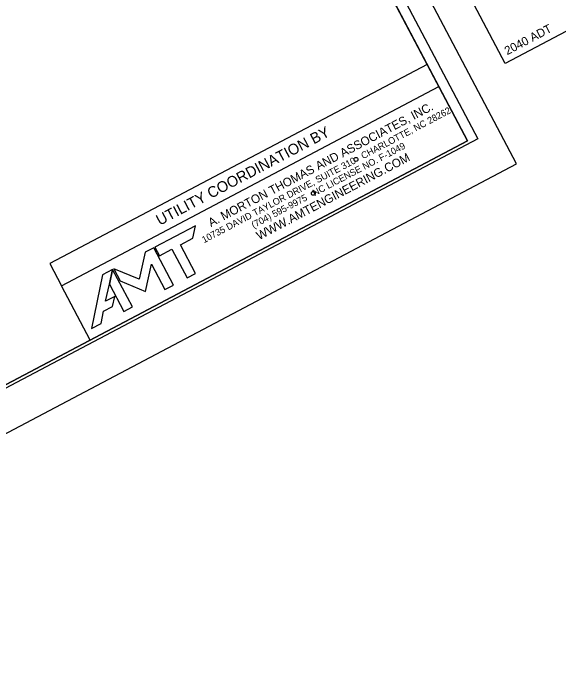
# Model space of a CAD drawing. Extents: x 1487051 to 1489241, y 497582 to 499399.
# Drawn here: x 1488789 to 1489072.9, y 498102.7 to 498446.4 of the extents above; entities that cross this region are included whole.
import ezdxf

# ---------------------------------------------------------------- set-up
doc = ezdxf.new("R2010")
doc.units = 0
for name, color, linetype in [('COGO Default Point Elevation', 7, 'Continuous'), ('Exist DTM Regular Point Cogo Elevation', 7, 'Continuous'), ('Exist Other Culture Sign Post Cogo Comment', 7, 'Continuous'), ('Exist Other Culture Sign Post Cogo Number', 7, 'Continuous'), ('Exist Roads EOP Cogo Point CELL', 7, 'Continuous'), ('Exist Structure Minor Pipes RCP 15 Inch Cogo Comment', 7, 'Continuous'), ('Exist Vegetation Woods Line Cogo Elevation', 7, 'Continuous'), ('Exist Vegetation Woods Line Cogo Number', 7, 'Continuous')]:
    doc.layers.add(name, color=color, linetype=linetype)

msp = doc.modelspace()

# ---------------------------------------------------------------- linework, layer by layer
at = {"layer": 'Exist DTM Regular Point Cogo Elevation'}
for points in [[(1487214.01, 498609.18), (1488227.42, 499144.32), (1488970.72, 498494.78), (1489030.74, 498381.1), (1487704.3, 497680.71)], [(1487208.66, 498608.09), (1488222.07, 499143.23), (1488965.37, 498493.68), (1489025.39, 498380), (1487698.94, 497679.61)], [(1487208.66, 498608.09), (1488222.07, 499143.23), (1488965.37, 498493.68), (1489025.39, 498380), (1487698.94, 497679.61)]]:
    msp.add_lwpolyline(points, close=True, dxfattribs=at)
at = {"layer": 'Exist Other Culture Sign Post Cogo Comment'}
msp.add_lwpolyline([(1488264.23, 499106.38), (1488223.12, 499143.79), (1487208.65, 498608.11), (1487698.94, 497679.61), (1489025.4, 498380.01), (1488871.95, 498670.61), (1488744.3, 498686.86)], close=True, dxfattribs=at)
at = {"layer": 'Exist Roads EOP Cogo Point CELL'}
msp.add_lwpolyline([(1487562.23, 497581.96), (1489050.94, 498368.04), (1488539.66, 499336.34), (1487050.94, 498550.27)], close=True, dxfattribs=at)
at = {"layer": 'Exist Structure Minor Pipes RCP 15 Inch Cogo Comment'}
for points in [[(1488535.14, 499308.53), (1487208.67, 498608.12), (1487698.94, 497679.61), (1489025.4, 498380.01)], [(1487698.94, 497679.61), (1487208.66, 498608.09), (1488358.21, 499215.12), (1488375.74, 499181.9), (1488552.62, 499275.32), (1489025.4, 498380.01)]]:
    msp.add_lwpolyline(points, close=True, dxfattribs=at)
at = {"layer": 'Exist Vegetation Woods Line Cogo Elevation'}
for points in [[(1488981.95, 498539.84), (1489169.07, 498638.65), (1489232.18, 498519.12), (1489045.06, 498420.32)], [(1488814.13, 498304.59), (1489010.48, 498408.27), (1489004.39, 498419.8), (1488808.04, 498316.13)], [(1488814.13, 498304.59), (1489010.48, 498408.27), (1489025.4, 498380.01), (1488829.05, 498276.33)]]:
    msp.add_lwpolyline(points, close=True, dxfattribs=at)
at = {"layer": 'Exist Vegetation Woods Line Cogo Number'}
msp.add_lwpolyline([(1488814.13, 498304.59), (1489010.48, 498408.27), (1489025.4, 498380.01), (1488829.05, 498276.33)], close=True, dxfattribs=at)
for points in [[(1488883.93, 498311.01), (1488876.03, 498325.97), (1488882.48, 498329.38), (1488883.85, 498335.8), (1488862.72, 498324.64), (1488865.08, 498320.19), (1488871.58, 498323.62), (1488879.48, 498308.66), (1488883.93, 498311.01)], [(1488857.9, 498301.64), (1488860.96, 498315.83), (1488867.95, 498302.58), (1488872.41, 498304.93), (1488862.16, 498324.34), (1488857.7, 498321.99), (1488854.57, 498307.95), (1488841.3, 498313.33), (1488844.56, 498307.15), (1488857.9, 498301.64)], [(1488839.03, 498305.46), (1488840.73, 498313.03), (1488835.53, 498310.28), (1488829.66, 498282.36), (1488834.7, 498285.02), (1488836.01, 498291.29), (1488840.63, 498293.73), (1488841.86, 498299.07), (1488837.08, 498296.55), (1488839.03, 498305.46)], [(1488850.98, 498293.61), (1488840.73, 498313.03), (1488839.03, 498305.46), (1488846.53, 498291.26), (1488850.98, 498293.61)]]:
    msp.add_lwpolyline(points, dxfattribs=at)
for centre in [(1488967.39, 498370.33), (1488945.15, 498352.67)]:
    msp.add_circle(centre, 1, dxfattribs=at)

# ---------------------------------------------------------------- texts
at = {"layer": 'COGO Default Point Elevation'}
msp.add_text('UTILITY COORDINATION BY', height=5.625, rotation=27.8351, dxfattribs=at).set_placement((1488865.23, 498335.77))
at = {"layer": 'Exist Other Culture Sign Post Cogo Number'}
msp.add_text('2040 ADT', height=4.444, rotation=27.8404, dxfattribs=at).set_placement((1489046.1, 498424.51))
at = {"layer": 'Exist Vegetation Woods Line Cogo Number'}
for s, height, p in [('10735 DAVID TAYLOR DRIVE, SUITE 310   CHARLOTTE, NC 28262', 3.5, (1488888.31, 498326.68)), ('A. MORTON THOMAS AND ASSOCIATES, INC.', 4.5, (1488891.9, 498335.08)), ('(704) 595-9975   NC LICENSE NO. F-1049', 3.5, (1488914.09, 498334.36)), ('WWW.AMTENGINEERING.COM', 4.5, (1488917.01, 498328.27))]:
    msp.add_text(s, height=height, rotation=27.8346, dxfattribs=at).set_placement(p)

doc.saveas('drawing.dxf')
